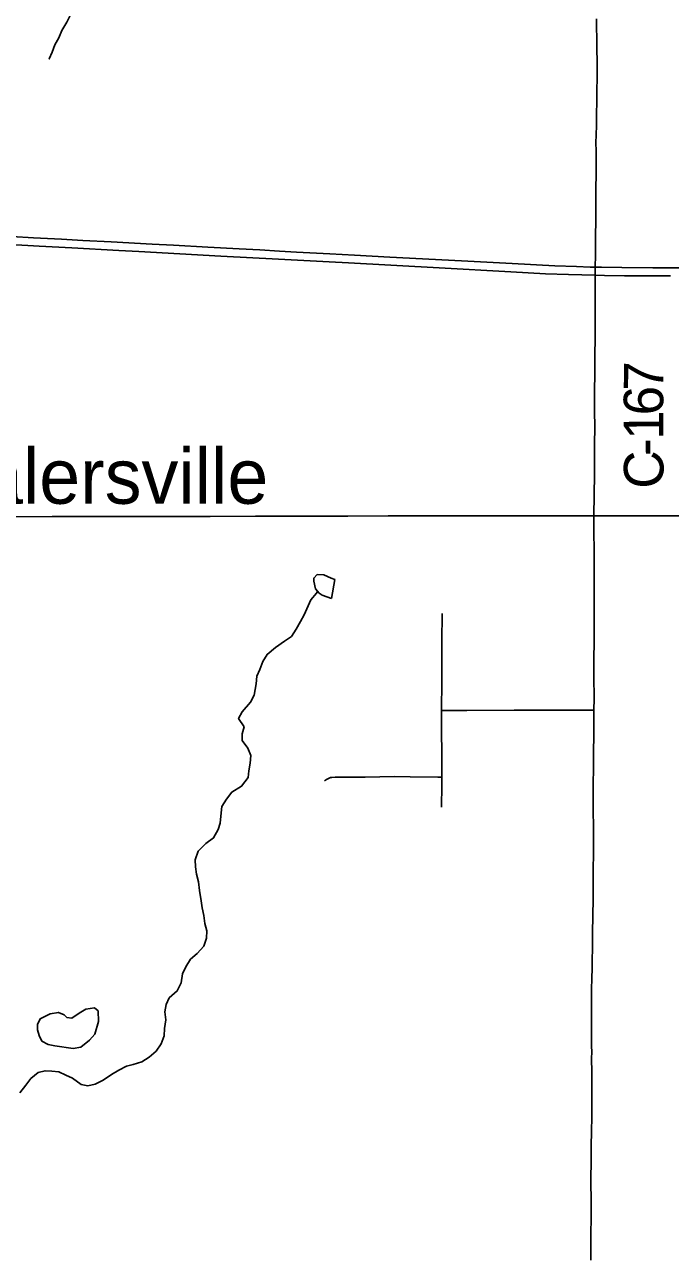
# Model space of a CAD drawing. Extents: x 0 to 34, y 0 to 22.
# Drawn here: x 5.233 to 7.549, y 14.409 to 18.822 of the extents above; entities that cross this region are included whole.
import ezdxf

# ---------------------------------------------------------------- set-up
doc = ezdxf.new("R2010")
doc.units = 0
for name, color, linetype in [('GM_X_County_Road', 7, 'Continuous'), ('GM_X_County_Road_Text', 7, 'Continuous'), ('GM_X_Interstate_Route', 7, 'Continuous'), ('GM_X_Minor_Lake', 7, 'Continuous'), ('GM_X_Minor_River', 7, 'Continuous'), ('GM_X_State_Route', 7, 'Continuous'), ('GM_X_Township_Road', 7, 'Continuous'), ('GM_X_Unincorporated_Text', 7, 'Continuous')]:
    doc.layers.add(name, color=color, linetype=linetype)

msp = doc.modelspace()

# ---------------------------------------------------------------- linework, layer by layer
at = {"layer": 'GM_X_County_Road'}
for points in [[(7.2744, 17.0624), (7.2765, 17.2118), (7.277, 17.3205), (7.2771, 17.3795), (7.2762, 17.44), (7.2768, 17.5069), (7.2774, 17.5752), (7.2779, 17.6203), (7.278, 17.6405), (7.2783, 17.6964), (7.2785, 17.7352), (7.2789, 17.7802), (7.2786, 17.8004), (7.2783, 17.8284), (7.2784, 17.8392), (7.2789, 17.9076), (7.279, 17.9243), (7.2791, 17.9418), (7.2792, 17.9537), (7.2795, 17.9962), (7.2803, 18.0428), (7.2803, 18.0832), (7.2807, 18.1018), (7.2815, 18.1483), (7.2814, 18.2151), (7.2822, 18.3067), (7.2821, 18.3408), (7.282, 18.3592), (7.282, 18.3638), (7.2822, 18.3742), (7.2817, 18.3959), (7.2822, 18.4316), (7.2831, 18.4579), (7.2837, 18.4811), (7.284, 18.4996), (7.2842, 18.5069), (7.2844, 18.5424), (7.2847, 18.5843), (7.2858, 18.6341), (7.286, 18.6821), (7.285, 18.7426), (7.284, 18.8433)], [(7.274, 16.3666), (7.2744, 16.3777), (7.2752, 16.3965), (7.2748, 16.4416), (7.2742, 16.4538), (7.274, 16.4922), (7.2745, 16.5365), (7.2746, 16.5706), (7.275, 16.5905), (7.2752, 16.6369), (7.2748, 16.6649), (7.2753, 16.7566), (7.2752, 16.9228), (7.2744, 17.0206), (7.2742, 17.0502), (7.2744, 17.0624)], [(7.2634, 14.3957), (7.2634, 14.4535), (7.2631, 14.495), (7.2639, 14.5425), (7.2639, 14.5727), (7.264, 14.6036), (7.2634, 14.6813), (7.2637, 14.7077), (7.2641, 14.7294), (7.2649, 14.7744), (7.2646, 14.8163), (7.2651, 14.8458), (7.2665, 14.9204), (7.2664, 14.9514), (7.2668, 14.9902), (7.2668, 15.0182), (7.2669, 15.0352), (7.2666, 15.0647), (7.2663, 15.074), (7.2661, 15.1132), (7.2663, 15.1471), (7.2661, 15.1577), (7.266, 15.1677), (7.2656, 15.189), (7.2653, 15.2242), (7.2654, 15.2536), (7.2654, 15.2739), (7.2658, 15.3176), (7.2662, 15.3687), (7.2671, 15.4027), (7.2679, 15.4446), (7.2696, 15.5392), (7.2695, 15.5547), (7.2704, 15.6424), (7.2712, 15.6772), (7.2717, 15.7131), (7.2713, 15.7753), (7.2721, 15.8056), (7.2724, 15.8419), (7.2731, 15.8823), (7.2726, 15.9225), (7.2726, 15.9624), (7.2722, 15.9907), (7.2721, 16.0608), (7.2734, 16.199), (7.2738, 16.2938), (7.274, 16.3666)]]:
    msp.add_lwpolyline(points, dxfattribs=at)
at = {"layer": 'GM_X_Interstate_Route'}
for points in [[(5.1865, 18.0631), (5.2649, 18.0588), (5.3653, 18.0534), (5.4412, 18.049), (5.5436, 18.0441), (5.6901, 18.036), (5.7671, 18.0317), (5.89, 18.0253), (6.0025, 18.0194), (6.0763, 18.0155), (6.1463, 18.0113), (6.2078, 18.0077), (6.3275, 18.0014), (6.4156, 17.9968), (6.5419, 17.9897), (6.7993, 17.9756), (6.9812, 17.966), (7.1344, 17.9586), (7.2113, 17.9555), (7.2606, 17.954), (7.2792, 17.9537), (7.3015, 17.9533), (7.3743, 17.9519), (7.4855, 17.9508), (7.6331, 17.951)], [(5.0725, 18.0406), (5.2443, 18.0308), (5.285, 18.0285), (5.4014, 18.0223), (5.5701, 18.0133), (5.6417, 18.0095), (5.9365, 17.9929), (6.1433, 17.982), (6.3249, 17.9722), (6.3941, 17.9684), (6.7198, 17.9508), (6.9767, 17.9369), (7.1011, 17.9301), (7.1834, 17.9267), (7.279, 17.9243), (7.3125, 17.9235), (7.3842, 17.9228), (7.4719, 17.9218), (7.5489, 17.9221)]]:
    msp.add_lwpolyline(points, dxfattribs=at)
at = {"layer": 'GM_X_Minor_Lake'}
for p, q in [((6.3335, 16.766), (6.3451, 16.8345)), ((5.341, 15.1632), (5.4067, 15.1538))]:
    msp.add_line(p, q, dxfattribs=at)
for points in [[(6.3451, 16.8345), (6.3318, 16.8391), (6.3061, 16.8511), (6.2824, 16.8518), (6.2693, 16.8393), (6.2703, 16.8279), (6.2763, 16.8004), (6.2888, 16.7854), (6.3003, 16.7779), (6.3335, 16.766)], [(5.4067, 15.1538), (5.4348, 15.1586), (5.4658, 15.1837), (5.4845, 15.2057), (5.4972, 15.2505), (5.4968, 15.2884), (5.4834, 15.2997), (5.4523, 15.2946), (5.4278, 15.281), (5.4024, 15.2627), (5.3844, 15.2653), (5.3748, 15.2747), (5.3539, 15.283), (5.3237, 15.2779), (5.2888, 15.2604), (5.2786, 15.2394), (5.2789, 15.2204), (5.2848, 15.2005), (5.2944, 15.1807), (5.3173, 15.1686), (5.341, 15.1632)]]:
    msp.add_lwpolyline(points, dxfattribs=at)
at = {"layer": 'GM_X_Minor_River'}
for points in [[(5.4608, 18.9959), (5.4768, 18.97), (5.4704, 18.9415), (5.4423, 18.9146), (5.4152, 18.8877), (5.3994, 18.8619), (5.3836, 18.8313), (5.3659, 18.8017), (5.3558, 18.775), (5.341, 18.7501), (5.3318, 18.7243), (5.3207, 18.6995), (5.3216, 18.7014)], [(5.216, 14.9956), (5.2375, 15.0224), (5.2552, 15.0464), (5.2815, 15.0685), (5.306, 15.0745), (5.3297, 15.0729), (5.3553, 15.0703), (5.381, 15.0583), (5.4048, 15.0481), (5.4354, 15.0247), (5.4591, 15.0203), (5.4855, 15.0263), (5.5147, 15.0409), (5.5448, 15.0611), (5.5702, 15.0766), (5.5975, 15.0912), (5.6221, 15.0962), (5.6532, 15.1061), (5.6795, 15.1225), (5.7048, 15.1447), (5.7225, 15.1705), (5.7326, 15.1991), (5.7342, 15.2257), (5.7386, 15.2571), (5.7355, 15.2855), (5.7399, 15.3112), (5.751, 15.3351), (5.7801, 15.3601), (5.794, 15.3887), (5.7993, 15.4211), (5.8104, 15.4469), (5.8271, 15.4736), (5.8515, 15.4948), (5.8749, 15.5207), (5.885, 15.5493), (5.8866, 15.575), (5.8787, 15.6015), (5.8756, 15.6309), (5.8696, 15.6574), (5.8655, 15.683), (5.8594, 15.7199), (5.8562, 15.7512), (5.8493, 15.7786), (5.8452, 15.8052), (5.844, 15.8299), (5.855, 15.8604), (5.8831, 15.8882), (5.9103, 15.9085), (5.9271, 15.9381), (5.9334, 15.9619), (5.9369, 15.9866), (5.9403, 16.0209), (5.9561, 16.0476), (5.9757, 16.0725), (6.0105, 16.0938), (6.0339, 16.1245), (6.0365, 16.1483), (6.0418, 16.1768), (6.0434, 16.2043), (6.0327, 16.2299), (6.0125, 16.2581), (6.0132, 16.2818), (6.0195, 16.3066), (6.0003, 16.3358), (6.0133, 16.3607), (6.0432, 16.3952), (6.0562, 16.42), (6.0633, 16.46), (6.0649, 16.4875), (6.076, 16.5114), (6.087, 16.54), (6.1028, 16.5658), (6.1328, 16.5909), (6.1648, 16.614), (6.1892, 16.6304), (6.2069, 16.6563), (6.2218, 16.684), (6.2357, 16.7079), (6.2597, 16.7613), (6.2793, 16.7853), (6.2835, 16.7918)]]:
    msp.add_lwpolyline(points, dxfattribs=at)
at = {"layer": 'GM_X_State_Route'}
msp.add_lwpolyline([(4.6577, 17.0584), (4.6719, 17.0586), (4.8165, 17.0591), (4.9422, 17.0592), (5.0742, 17.0593), (5.1907, 17.0592), (5.332, 17.0595), (5.4299, 17.0596), (5.6552, 17.0603), (5.7656, 17.0598), (5.8976, 17.0605), (6.0606, 17.061), (6.1943, 17.0607), (6.2875, 17.0608), (6.3916, 17.0608), (6.5361, 17.0621), (6.7302, 17.0625), (6.7877, 17.0628), (6.8854, 17.0627), (7.2296, 17.0624), (7.2744, 17.0624), (7.2979, 17.0623), (7.5027, 17.0624), (7.7699, 17.0625)], dxfattribs=at)
at = {"layer": 'GM_X_Township_Road'}
for points in [[(6.7281, 16.365), (6.7281, 16.3693), (6.7289, 16.4655), (6.7291, 16.5322), (6.7292, 16.5741), (6.7292, 16.6331), (6.7297, 16.6921), (6.7297, 16.7123)], [(6.7292, 16.1266), (6.7292, 16.1831), (6.7285, 16.2126), (6.7279, 16.2901), (6.7279, 16.3212), (6.7281, 16.365)], [(6.7281, 16.365), (6.7436, 16.365), (6.8181, 16.3651), (6.9888, 16.3656), (7.1006, 16.3667), (7.274, 16.3666)], [(6.3076, 16.1132), (6.3155, 16.1181), (6.3252, 16.123), (6.3296, 16.1246), (6.3342, 16.1252), (6.3465, 16.1262), (6.3822, 16.1263), (6.4272, 16.126), (6.4536, 16.1264), (6.5063, 16.1277), (6.5575, 16.128), (6.6149, 16.1273), (6.7141, 16.1267), (6.7292, 16.1266)], [(6.7282, 16.0186), (6.7293, 16.0978), (6.7292, 16.1266)]]:
    msp.add_lwpolyline(points, dxfattribs=at)

# ---------------------------------------------------------------- texts
at = {"layer": 'GM_X_County_Road_Text'}
for s, rotation, p in [('7', 89.3599, (7.5233, 17.5095)), ('6', 89.8074, (7.523, 17.4223)), ('1', 90.1249, (7.5232, 17.335)), ('-', 90.3279, (7.5235, 17.2768)), ('C', 90.4098, (7.5244, 17.1602))]:
    msp.add_text(s, height=0.142, rotation=rotation, dxfattribs=at).set_placement(p)
at = {"layer": 'GM_X_Unincorporated_Text'}
msp.add_text('Shalersville', height=0.197443, rotation=0, dxfattribs=at).set_placement((4.7567, 17.1057))

doc.saveas('drawing.dxf')
